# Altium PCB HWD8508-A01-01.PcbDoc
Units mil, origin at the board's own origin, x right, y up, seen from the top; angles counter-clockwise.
Board outline 2946.92 x 2010.03 mil, 2 copper layers (TopLayer, BottomLayer); 46 components, 92 nets, 462 pads, 19 vias.
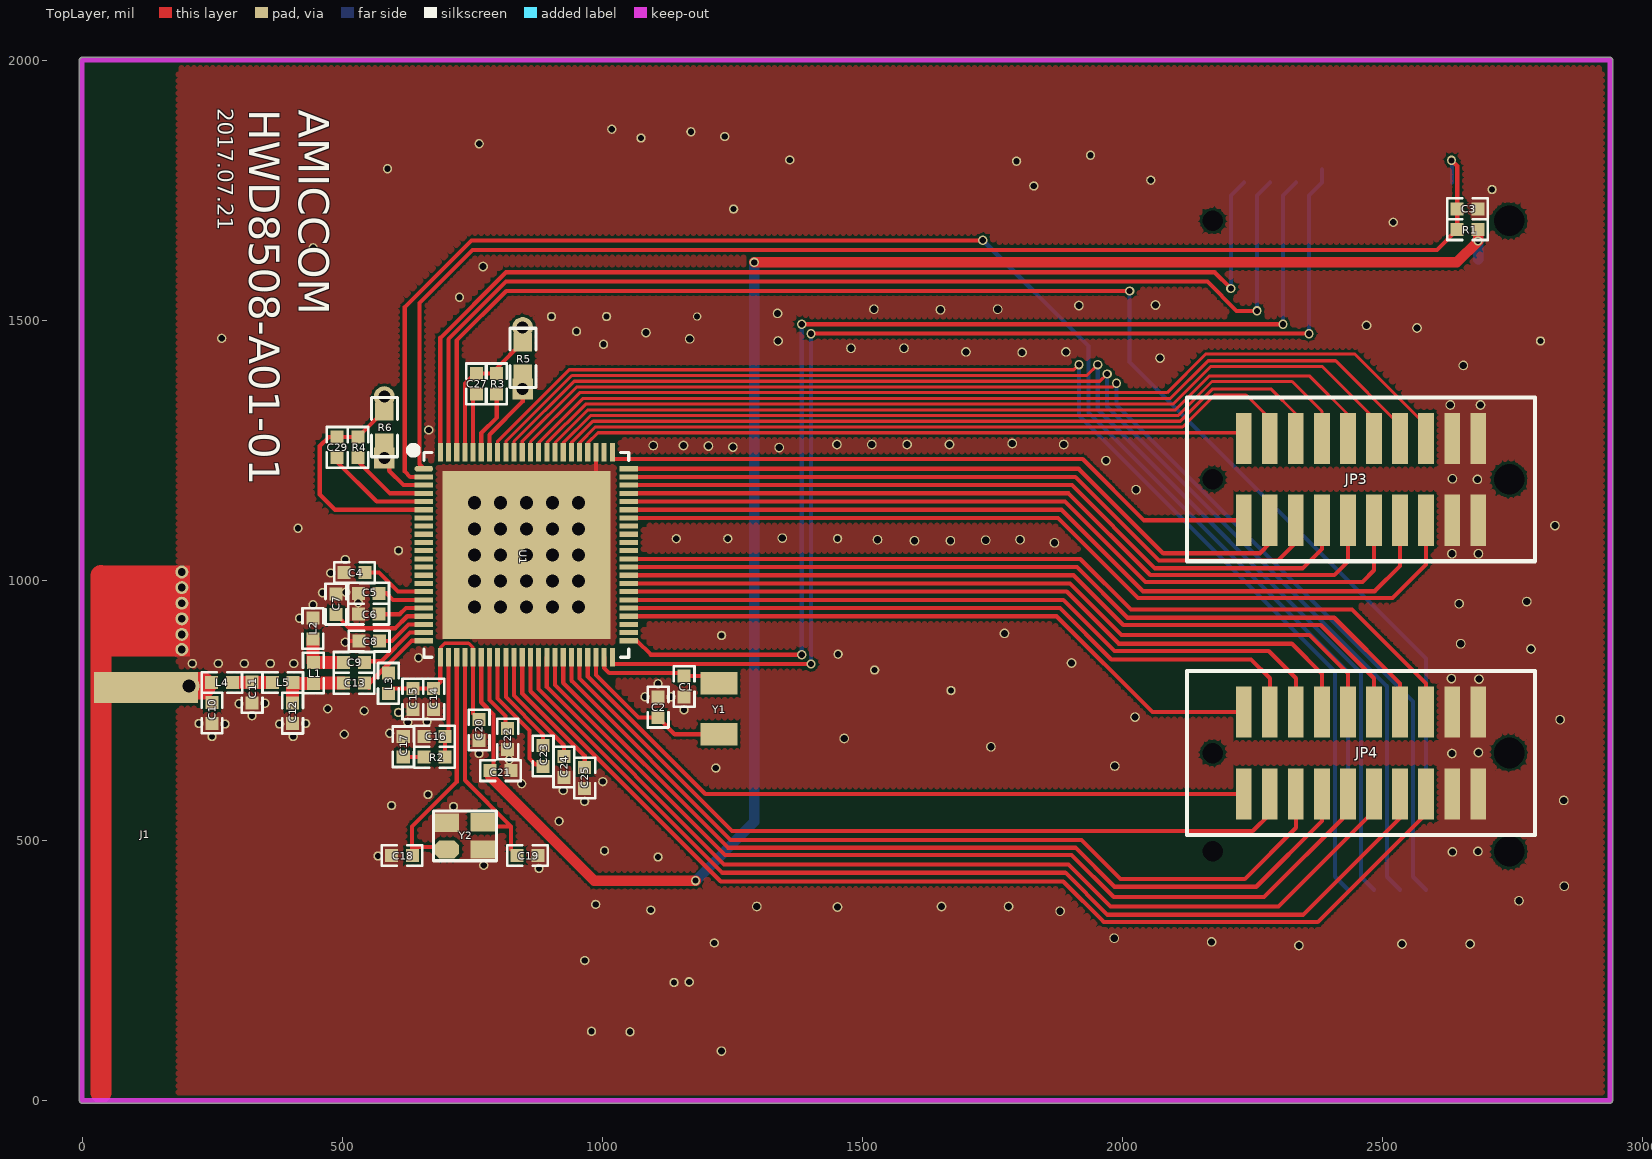
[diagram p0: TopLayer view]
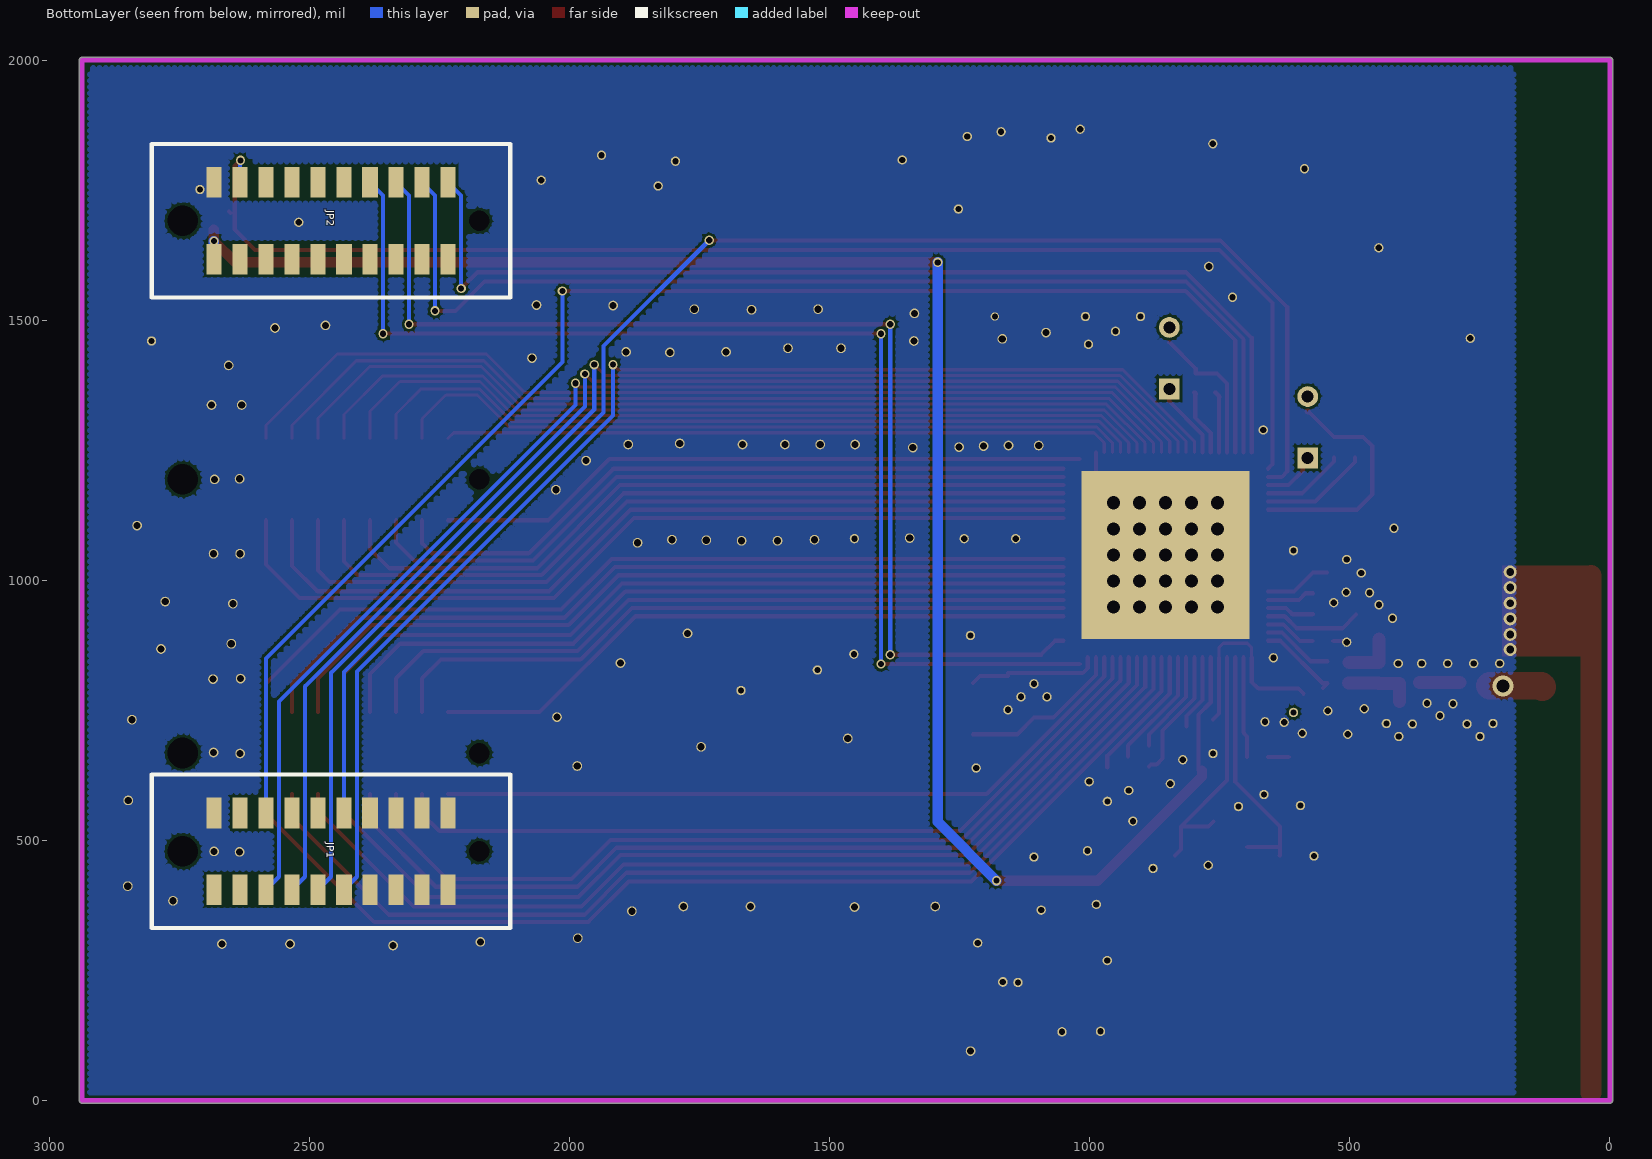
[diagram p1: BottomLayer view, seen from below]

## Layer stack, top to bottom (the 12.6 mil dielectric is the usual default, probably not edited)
TopSolder: solder mask 0.4, Solder Resist, Dk 3.5
TopLayer: signal copper 1.4
Dielectric1: dielectric 12.6, FR-4, Dk 4.8
BottomLayer: signal copper 1.4
BottomSolder: solder mask 0.4, Solder Resist, Dk 3.5

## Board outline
-5.01,0.34 ccw(c-0.01,0) -0.01,-5.01 2936.89,-5.01 ccw(c2936.89,0) 2941.91,0 2941.91,2000 ccw(c2936.89,2000) 2936.89,2005.01 -0.01,2005.01 ccw(c-0.01,2000) -5.01,1999.66

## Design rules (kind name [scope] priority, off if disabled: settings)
Clearance Clearance_4 [InNet('NetC19_1')] p1: gap=14
Clearance Clearance_3 [InNet('NetC18_2')] p2: gap=14
Clearance Clearance_2 [InNet('NetC4_2')] p3: gap=14
Clearance [All] p4 off: gap=8
Clearance Clearance_1 [All] p5: gap=5
ComponentClearance [All] p1 off: gap=10 collisioncheckmode=3 verticalgap=10 showdistances=FALSE
FabricationTestPointUsage TestPointUsage [All] p1: valid=0 allowmultiple=FALSE
FabricationTestpoint Testpoint [All] p1: side=3 testpointundercomponent=TRUE minsize=40 maxsize=100 preferedsize=60 minholesize=20 maxholesize=40 preferedholesize=32 testpointgrid=1 allowsidetop=TRUE allowsidebottom=TRUE usegrid=TRUE gridtolerance=0.01
HoleSize [All] p1: absolutevalues=TRUE maxlimit=200 minlimit=1 maxpercent=80.000 minpercent=20.000
PolygonConnect [All] p1: connectstyle=Direct reliefconductorwidth=10 reliefentries=4 polygonreliefangle="90 Angle" airgapwidth=10
RoutingVias [All] p1: holewidth=28 width=50 viastyle="Through Hole" minholewidth=28 minwidth=50 maxholewidth=28 maxwidth=50
SilkToSolderMaskClearance SilkscreenOverComponentPads [IsPad] p1: minsilkscreentomaskgap=10 clearancetoexposedcopper=TRUE
SolderMaskExpansion [All] p1: expansion=4
Width [All] p1: maxlimit=100 minlimit=6 preferedwidth=10
25 further rules are at their usual default settings.

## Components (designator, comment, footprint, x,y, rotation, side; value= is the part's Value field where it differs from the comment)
C1 "27p" 0402#1 1157.25,816.02 r270 top
C2 "27p" 0402#1 1107.25,736.02 r90 top
C3 "1U" 0402#1 2643.29,1714.02 r0 top
C4 "1uF" 0402#1 543.84,1014.71 r180 top
C5 "1uF" 0402#1 571.04,975.02 r180 top
C6 "330pF" 0402#1 571.04,935.02 r180 top (schematic designator C7)
C7 "120pF" 0402#1 488.04,934.02 r90 top
C8 "1uF" 0402#1 572.04,883.02 r180 top
C9 "2.7pF" 0402#1 542.84,842.23 r180 top
C10 "NC" 0402#1 249.84,724.71 r90 top
C11 "1pF" 0402#1 326.84,764.6 r90 top
C12 "1.2pF" 0402#1 404.84,764.6 r270 top
C13 "3.3pF" 0402#1 542.84,802.1 r180 top
C14 "100pF" 0402#1 676.04,792.02 r270 top
C15 "0.1uF" 0402#1 635.99,792 r270 top
C16 "3.3nF" 0402#1 697.45,700.02 r180 top
C17 "NC" 0402#1 617.45,660.02 r90 top
C18 "NC" 0402#1 635.04,471.02 r180 top
C19 "NC" 0402#1 836.04,471.02 r0 top
C20 "1uF" 0402#1 763.18,732.17 r270 top
C21 "1uF" 0402#1 784.18,634.17 r0 top
C22 "2.2uF" 0402#1 818.18,715.17 r270 top
C23 "47nF" 0402#1 886.18,642.17 r90 top (schematic designator C35)
C24 "1uF" 0402#2 926.18,641.17 r270 top (schematic designator C32)
C25 "1uF" 0402#2 966.18,620.17 r270 top (schematic designator C31)
C27 "NC" 0402#1 758.29,1397.58 r270 top (schematic designator C203)
C29 "820pF" 0402#1 490.43,1275.53 r270 top (schematic designator C103)
J1 "ANTENNA" ANT 122.84,793.94 r0 top
JP1 "HEADER 10X2B" YAB-V45P-2X 2173.45,479 r0 bottom locked
JP2 "HEADER 10X2B" YAB-V45P-2X 2173.45,1691 r0 bottom locked
JP3 "HEADER 10X2B" PAB-V16P-2X 2173.45,1194 r0 top locked
JP4 "HEADER 10X2B" PAB-V16P-2X 2173.45,668 r0 top locked
L1 "2.2nH" 0402#1 444.84,801.6 r90 top
L2 "1.2nH" 0402#1 443.84,887.6 r90 top
L3 "2.7nH" 0402#1 588.99,782 r90 top
L4 "1.8nH" 0402#1 248.84,803.6 r0 top
L5 "2.2nH" 0402#1 365.84,803.6 r0 top
R1 "100K" 0402#1 2683.29,1674.02 r180 top
R2 "NC" 0402#1 697.45,660.02 r180 top
R3 "NC" 0402#1 796.29,1357.58 r90 top (schematic designator R202)
R4 "10k" 0402#1 530.43,1235.53 r90 top (schematic designator R102)
R5 "NC" TR 847,1427 r0 top
R6 "NXRT15XH103FA1B" TR 581,1294 r0 top
U1 "A8508" "QFN 10*10 88L" 854.04,1049.02 r0 top
Y1 "32.768KHz" XTAL\32.768K\SMD 1224.11,704.06 r90 top (schematic designator Y2)
Y2 "16MHz, 9pF" XTAL_3.2*2.5 735.66,508.52 r270 top (schematic designator Y3)

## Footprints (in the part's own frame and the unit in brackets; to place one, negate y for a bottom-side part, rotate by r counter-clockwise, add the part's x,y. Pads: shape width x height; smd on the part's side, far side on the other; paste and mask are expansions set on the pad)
0402#1 [mil]
  rect 25x25 smd: 1(0,0) 2(40,0)
  silkscreen extent -19,-20 59,20
0402#2 [mil]
  rect 25x25 smd: 1(-20,0) 2(20,0)
  silkscreen extent -39,-20 39,20
ANT [mil]
  rect 200x60 smd: 1(0,0)
  TopLayer region: -43.41,234.83 -43.41,59.83 85.02,59.83 85.02,234.83
  TopLayer region: -78.98,60 -31.98,60 -31.98,210 -78.98,210
  TopLayer lines w40: -86.57,-779 -86.57,-708.42 -86.57,214.17 ; -86.57,215 65,214.83
PAB-V16P-2X [mm]
  rect 0.76x2.5 smd: 1(1.52,-2) 2(2.79,-2) 3(4.06,-2) 4(5.33,-2) 5(6.6,-2) 6(7.87,-2) 7(9.14,-2) 8(10.41,-2) 9(11.68,-2) 10(12.95,-2) 11(1.52,2) 12(2.79,2) 13(4.06,2) 14(5.33,2) 15(6.6,2) 16(7.87,2) 17(9.14,2) 18(10.41,2) 19(11.68,2) 20(12.95,2)
  oval 0x1 hole 1: ""(0,0)
  oval 0x1.5 hole 1.5: ""(14.47,0)
  silkscreen extent -1.26,-4 15.74,4
"QFN 10*10 88L" [mm]
  oct 0.9x0.25 smd: 1(-5,4.2)
  rect 0.9x0.25 smd: 2(-5,3.8) 3(-5,3.4) 4(-5,3) 5(-5,2.6) 6(-5,2.2) 7(-5,1.8) 8(-5,1.4) 9(-5,1) 10(-5,0.6) 11(-5,0.2) 12(-5,-0.2) 13(-5,-0.6) 14(-5,-1) 15(-5,-1.4) 16(-5,-1.8) 17(-5,-2.2) 18(-5,-2.6) 19(-5,-3) 20(-5,-3.4) 21(-5,-3.8) 22(-5,-4.2) 45(5,-4.2) 46(5,-3.8) 47(5,-3.4) 48(5,-3) 49(5,-2.6) 50(5,-2.2) 51(5,-1.8) 52(5,-1.4) 53(5,-1) 54(5,-0.6) 55(5,-0.2) 56(5,0.2) 57(5,0.6) 58(5,1) 59(5,1.4) 60(5,1.8) 61(5,2.2) 62(5,2.6) 63(5,3) 64(5,3.4) 65(5,3.8) 66(5,4.2)
  rect 0.25x0.9 smd: 23(-4.2,-5) 24(-3.8,-5) 25(-3.4,-5) 26(-3,-5) 27(-2.6,-5) 28(-2.2,-5) 29(-1.8,-5) 30(-1.4,-5) 31(-1,-5) 32(-0.6,-5) 33(-0.2,-5) 34(0.2,-5) 35(0.6,-5) 36(1,-5) 37(1.4,-5) 38(1.8,-5) 39(2.2,-5) 40(2.6,-5) 41(3,-5) 42(3.4,-5) 43(3.8,-5) 44(4.2,-5) 67(4.2,5) 68(3.8,5) 69(3.4,5) 70(3,5) 71(2.6,5) 72(2.2,5) 73(1.8,5) 74(1.4,5) 75(1,5) 76(0.6,5) 77(0.2,5) 78(-0.2,5) 79(-0.6,5) 80(-1,5) 81(-1.4,5) 82(-1.8,5) 83(-2.2,5) 84(-2.6,5) 85(-3,5) 86(-3.4,5) 87(-3.8,5) 88(-4.2,5)
  round 0.635 hole 0.635: ""(-2.54,-2.54) ""(-2.54,-1.27) ""(-2.54,0) ""(-2.54,1.27) ""(-2.54,2.54) ""(-1.27,-2.54) ""(-1.27,-1.27) ""(-1.27,0) ""(-1.27,1.27) ""(0,-2.54) ""(0,-1.27) ""(0,1.27) ""(0,2.54) ""(1.27,-2.54) ""(1.27,-1.27) ""(1.27,0) ""(1.27,1.27) ""(1.27,2.54) ""(2.54,-2.54) ""(2.54,-1.27) ""(2.54,0) ""(2.54,1.27) ""(2.54,2.54)
  round 0.762 hole 0.635: ""(-1.27,2.54)
  rect 8.2x8.2 hole 0.635: ""(0,0)
  silkscreen extent -5.62,-5 5,5.21
TR [mil]
  rect 40x40 hole 23: 1(0,-59.06)
  rect 35x35 smd: 1(0,-29.5) 2(0,30.5)
  round 40 hole 23: 2(0,59.06)
  silkscreen extent -24,-56 26,58
XTAL\32.768K\SMD [mm]
  rect 1.1x1.8 smd: 1(0,0) 2(2.5,0)
XTAL_3.2*2.5 [mm]
  oct 0.9x1.2 smd: 1(0.66,-0.87)
  rect 0.9x1.2 smd: 2(0.66,0.87) 3(-0.66,0.87) 4(-0.65,-0.87)
  silkscreen extent -1.22,-1.53 1.21,1.55
YAB-V45P-2X [mm]
  rect 0.74x1.5 smd: 1(1.52,1.875) 2(2.79,1.875) 3(4.06,1.875) 4(5.33,1.875) 6(7.87,1.875) 7(9.14,1.875) 8(10.41,1.875) 9(11.68,1.875) 10(12.95,1.875) 11(1.52,-1.875) 12(2.79,-1.875) 13(4.06,-1.875) 15(6.6,-1.875) 16(7.87,-1.875) 17(9.14,-1.875) 18(10.41,-1.875) 19(11.68,-1.875) 20(12.95,-1.875)
  rect 0.76x1.5 smd: 5(6.6,1.875) 14(5.33,-1.875)
  oval 0x1 hole 1: ""(0,0)
  oval 0x1.5 hole 1.5: ""(14.47,0)
  silkscreen extent -1.52,-3.75 15.98,3.75

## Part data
C1 C2 C23: library part C/0603, "Chip C"
C3: library part C/0402, "Chip C"
C4 C5 C6 C7 C8 C9 C10 C11 C12 C13 C14 C15 C16 C17 C18 C19 C20 C21 C22 C24 C25 C27 C29: library part CAP
JP1 JP2 JP3 JP4: "Pitch 2.54mm"
L1 L2 L3 L4 L5: library part L/0402, "Chip L"
R1: library part R/0603, "Chip  R"
R2 R3 R4 R5 R6: library part RES1
U1: library part "ams100_3a wo DCDC"
Y1: library part CRYSTAL, "Crystal"
Y2: library part CRYSTAL/5*3.2

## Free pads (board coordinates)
  round 18 hole 12: A(212.04,840.02) A(224.8,724.71) A(249.8,699.71) A(262.04,840.02) A(268.45,1465.02) A(274.8,723.71) A(301.8,762.71) A(312.04,840.02) A(326.8,739.71) A(351.8,763.71) A(362.04,840.02) A(379.8,723.71) A(405.8,699.71) A(407.04,840.02) A(415.29,1100.02) A(418.04,927.02) A(429.8,724.71) A(444.04,953.02) A(444.29,1639.02) A(462.04,976.02) A(472.29,753.02) A(478.04,1014.02) A(503.99,704) A(506.04,881.02) A(507.04,977.02) A(531.04,957.02) A(542.29,749.02) A(569.04,470.02) A(587.29,1791.02) A(591.29,706.02) A(595.04,567.02) A(608.29,1057.02) A(626.29,727.02) A(646.99,851) A(663.29,728.02) A(665.18,588.17) A(666.45,1289.02) A(714.04,565.02) A(725.45,1544.02) A(763.04,667.02) A(763.29,1839.02) A(772.18,452.17) A(821.04,655.02) A(845.04,609.02) A(878.18,446.17) A(902.29,1507.02) A(917.04,537.02) A(925.04,596.02) A(950.43,1478.47) A(966.04,575.02) A(966.29,269.02) A(979.29,133.02) A(987.29,377.02) A(1001.04,613.02) A(1002.43,1453.47) A(1004.29,480.02) A(1008.29,1507.02) A(1018.29,1867.02) A(1053.29,132.02) A(1074.29,1850.02) A(1082.25,776.02) A(1093.29,366.02) A(1107.25,801.02) A(1107.29,468.02) A(1132.25,776.02) A(1137.99,227) A(1142.29,1080.02) A(1157.25,751.02) A(1170.29,1862.02) A(1215.29,303.02) A(1218.29,639.02) A(1229.29,894.02) A(1235.29,1853.02) A(1241.29,1080.02) A(1252.43,1713.47) A(1360.29,1808.02) A(1452.29,1080.02) A(1453.29,858.02) A(1523.43,827.47) A(1670.29,788.02) A(1796.29,1805.58) A(1829.43,1758.02) A(1938.29,1817.02) A(2054.29,1769.02) A(2520.29,1688.02) A(2710.29,1751.02) A(2803.29,1460.02) ""(608.29,746.02)
  round 18 hole 12 mask+4: A(506.04,1040.02)
  round 18.7 hole 13.78: A(771,1603) A(1084,1476) A(1098,1259) A(1156,1259) A(1168,1464) A(1204,1258) A(1229,95) A(1251,1256) A(1297,373) A(1337,1513) A(1338,1460) A(1340,1255) A(1346,1081) A(1451,1261) A(1452,372) A(1465,696) A(1478,1446) A(1518,1261) A(1522,1521) A(1529,1078) A(1580,1446) A(1586,1261) A(1600,1076) A(1650,1520) A(1652,373) A(1667.26,1261) A(1669,1076) A(1699,1439) A(1737,1077) A(1747,680) A(1760,1521) A(1773,898) A(1781,373) A(1788,1263) A(1803,1078) A(1807,1438) A(1869,1072.05) A(1880,364) A(1887,1261) A(1891,1439) A(1902,841) A(1916,1528.05) A(1968,1230) A(1984,312) A(1985,643) A(2024,737) A(2026,1174) A(2063.26,1529) A(2072,1427) A(2171.26,305) A(2339,298) A(2469,1490) A(2537,301) A(2566,1485) A(2630,1337) A(2632,811) A(2633,667) A(2633,1051) A(2634,478) A(2634,1195) A(2647,955) A(2650,878) A(2655,1413) A(2668,301) A(2682,1194) A(2683,479) A(2684,669) A(2684,1051) A(2685,810) A(2688,1337) A(2762,384) A(2777,959) A(2785,868) A(2831,1105) A(2841,732) A(2848,577) A(2849,412)
  round 18.7 hole 12.01: A(1167,228)
  round 16 hole 12: A(1182.29,1507.02)
  round 25 hole 15: ""(191.84,866.94) ""(191.84,895.94) ""(191.84,925.94) ""(191.84,955.94) ""(191.84,985.94) ""(191.84,1015.94)

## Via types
v1: diameter 18, hole 12, TopLayer to BottomLayer, tented both sides, 18 vias
v2: diameter 40, hole 25, TopLayer to BottomLayer, 1 vias

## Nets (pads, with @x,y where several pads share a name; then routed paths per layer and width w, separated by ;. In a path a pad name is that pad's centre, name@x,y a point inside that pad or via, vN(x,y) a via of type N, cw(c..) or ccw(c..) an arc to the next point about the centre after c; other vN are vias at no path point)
BG: C6.1 U1.18 | length 91.2
  TopLayer w8: C6.1 571.34,934.71 610.58,934.71 622.52,946.65 U1.18
CP_LCD: C25.1 U1.33 | length 261.7
  TopLayer w8: U1.33 846.16,782.7 966.18,662.68 C25.1
CPPA: C23.1 U1.30 | length 252.6
  TopLayer w8: U1.30 798.92,772.75 860.18,711.49 860.18,657.17 871.18,646.17 882.18,646.17 C23.1
CPPB: C23.2 U1.31 | length 199.6
  TopLayer w8: U1.31 814.67,775.39 886.18,703.87 C23.2
GND: C1.2 C2.2 C3.2 C4.2 C5.2 C6.2 C7.2 C8.2 C10.1 C11.1 C12.2 C14.2 C15.2 C16.2 C17.2 C18.2 C19.2 C20.2 C21.2 C22.2 C24.2 C25.2 JP1.1 JP1.2 JP1.3 JP1.4 JP1.11 JP1.12 JP1.13 JP1.14 JP1.20 JP2.20 JP3.9 JP3.10 JP3.19 JP3.20 JP4.9 JP4.10 JP4.19 JP4.20 L2.2 pad.@191.84,866.94 pad.@191.84,895.94 pad.@191.84,925.94 pad.@191.84,955.94 pad.@191.84,985.94 pad.@191.84,1015.94 pad.A U1. U1.69 Y2.2 Y2.4 | length 137.7
  TopLayer w8: pad.A@506.04,881.02 508.04,883.02 C8.2 ; U1.@954.04,1149.02 987.89,1182.87 U1.69
LCDCAP_R33: C22.1 U1.29 | length 145.8
  TopLayer w8: U1.29 783.17,770.11 814.18,739.1 C22.1@814.18,719.17
LPF: C16.1 R2.1 U1.24 | length 195
  TopLayer w8: R2.1 C16.1 704.43,707 U1.24
NetC9_2: C9.2 L1.2 L2.1 | length 103
  TopLayer w25: L1.2@443.84,842.23 C9.2@501.84,842.23 ; L1.2@443.84,842.6 L2.1
NetC10_2: C10.2 J1.1 L4.1 | length 101.8
  TopLayer w53: J1.1@129.84,794.94 131.84,796.94 v2(205.84,796.94) 230.84,796.94
NetC11_2: C11.2 L4.2 L5.1 | length 78
  TopLayer w25: L4.2@287.84,803.6 L4.2 L5.1
NetC12_1: C12.1 C13.2 L1.1 L5.2 | length 133
  TopLayer w25: C12.1@404.84,766.6 404.84,801.6 L1.1 ; L1.1@444.84,802.1 C13.2
NetC17_1: C17.1 R2.2 | length 40
  TopLayer w8: C17.1 R2.2
P0.0: C29.1 R4.2 R6.2 U1.6 | length 457.4
  TopLayer w8: R6.2@581,1324.5 579.4,1324.5 R4.2 C29.1 474.53,1275.53 457,1258 457,1165 486.37,1135.63 U1.6
  TopLayer w12: R6.2@581,1324.5 R6.2@581.5,1324.5
P0.1: C29.2 U1.5 | length 206.3
  TopLayer w8: C29.2 490.43,1227.47 566.52,1151.38 U1.5
P0.2: R4.1 U1.4 | length 159.2
  TopLayer w8: R4.1 530.43,1228.47 591.78,1167.13 U1.4
P0.3: R6.1 U1.3 | length 106.5
  TopLayer w8: R6.1@581,1234.94 590.43,1225.52 590.43,1210.56 618.11,1182.87 U1.3
P0.4/DEBUG_EN: JP1.15 U1.2 | length 2912.5
  TopLayer w8: U1.2 630.75,1198.62 620.45,1208.93 620.45,1525.02 748.45,1653.02 v1@1731.29,1653.02
  BottomLayer w8: v1(1731.29,1653.58) 1934.29,1450.58 1934.29,1322.58 2433.29,823.58 JP1.15
P0.5: JP2.11 U1.88 | length 2019.2
  TopLayer w8: U1.88 688.68,1466.02 814.68,1592.02 2177.1,1592.02 v1(2208.29,1560.82)
  BottomLayer w8: v1(2208.29,1560.82) 2208.29,1739.82 JP2.11
P0.6: JP2.12 U1.87 | length 2097.8
  TopLayer w8: U1.87 704.43,1463.38 815.06,1574.02 2163.1,1574.02 2219.29,1517.82 v1(2258.29,1517.82)
  BottomLayer w8: v1(2258.29,1517.82) 2258.29,1739.82 JP2.12
P0.7/GIO1: JP1.18 U1.86 | length 2786.9
  TopLayer w8: U1.86 720.18,1460.75 815.45,1556.02 v1(2013.51,1556.02)
  BottomLayer w8: v1(2013.51,1556.02) 2013.51,1419.49 2583.29,849.7 JP1.18
P1.0: C27.1 R3.2 R5.2 U1.85 | length 282.6
  TopLayer w8: U1.85 735.93,1377.98 755.53,1397.58 C27.1 R3.2 796.29,1406.79 R5.2@847,1457.5 ; R5.2@847,1485 R5.2@847,1486.06
P1.1: C27.2 U1.84 | length 129.5
  TopLayer w8: C27.2@750.67,1352.24 C27.2@751.67,1353.24 ; U1.84 C27.2@751.67,1353.24 ; C27.2@757.29,1360.58 751.67,1354.96 C27.2@751.67,1353.24 ; C27.2@759.45,1361.02 C27.2@751.67,1353.24
P1.2/GIO2: R3.1 U1.83 | length 131.5
  TopLayer w8: U1.83 767.42,1282.99 797.29,1312.87 R3.1@797.29,1358.87 ; R3.1@796.29,1357.87 R3.1@797.29,1358.87 ; R3.1@797.29,1360.58 R3.1@797.29,1358.87 ; R3.1@799.45,1361.02 R3.1@797.29,1358.87
P1.3/CKO: R5.1 U1.82 | length 148.5
  TopLayer w8: U1.82 783.17,1279.74 847,1343.57 R5.1@847,1367.94
P1.4/TTDIO: JP1.5 U1.81 | length 2423.3
  TopLayer w6: U1.81 798.92,1267.21 936.29,1404.58 1906.29,1404.58 v1(1916.29,1414.58)
  BottomLayer w8: v1(1916.29,1414.58) 1916.29,1316.58 2408.29,824.58 2408.29,430.18 JP1.5
P1.5/TTCLK: JP1.6 U1.80 | length 2449.1
  TopLayer w6: U1.80 814.67,1266.76 941.49,1393.58 1931.29,1393.58 v1(1952.29,1414.58)
  BottomLayer w8: v1(1952.29,1414.58) 1952.29,1328.18 2458.29,822.18 2458.29,430.18 JP1.6
P1.6: JP1.7 U1.79 | length 2439.3
  TopLayer w6: U1.79 830.41,1266.95 946.04,1382.58 1956.29,1382.58 v1(1970.29,1396.58)
  BottomLayer w8: v1(1970.29,1396.58) 1970.29,1334.18 2508.29,796.18 2508.29,430.18 JP1.7
P1.7: JP1.8 U1.78 | length 2429.4
  TopLayer w6: U1.78 846.16,1267.15 950.6,1371.58 1981.29,1371.58 v1(1988.29,1378.58)
  BottomLayer w8: v1(1988.29,1378.58) 1988.29,1337.18 2558.29,767.18 2558.29,430.18 JP1.8
P2.0/C0: JP3.18 U1.77 | length 1893.6
  TopLayer w6: U1.77 861.91,1265.95 956.54,1360.58 2085.58,1360.58 2160,1435 2446.52,1435 2583.3,1298.23 JP3.18
P2.1/C1: JP3.17 U1.76 | length 1816
  TopLayer w6: U1.76 877.66,1264.07 963.17,1349.58 2092.21,1349.58 2164.63,1422 2409.52,1422 2533.3,1298.23 JP3.17
P2.2/C2: JP3.16 U1.75 | length 1749
  TopLayer w6: U1.75 893.41,1264.07 967.92,1338.58 2096.96,1338.58 2169.38,1411 2384,1411 2483.3,1311.7 JP3.16
P2.3/C3: JP3.15 U1.74 | length 1672.5
  TopLayer w6: U1.74 909.15,1264.07 972.67,1327.58 2101.71,1327.58 2167.13,1393 2359,1393 2433.3,1318.7 JP3.15
P2.4/S0: JP3.14 U1.73 | length 1601.2
  TopLayer w6: U1.73 924.9,1264.07 977.41,1316.58 2106.46,1316.58 2171.88,1382 2326.05,1382 2383.3,1324.76 JP3.14
P2.5/S1: JP3.13 U1.72 | length 1521
  TopLayer w6: U1.72 940.65,1264.25 981.98,1305.58 2111.03,1305.58 2173.44,1368 2285,1368 2333.3,1319.7 JP3.13
P2.6/S2: JP3.12 U1.71 | length 1439.8
  TopLayer w6: U1.71 956.4,1264.44 986.54,1294.58 2115.58,1294.58 2177,1356 2237.48,1356 2283.3,1310.18 JP3.12
P2.7/S3: JP3.11 U1.70 | length 1291.9
  TopLayer w6: U1.70 972.15,1264.07 991.66,1283.58 2222.45,1283.58 JP3.11
P3.0: U1.47
P3.1: U1.46
P3.2: JP2.13 U1.45 | length 2186.6
  TopLayer w8: U1.45 1066.6,883.66 1093.25,857.02 v1(1383.29,857.02) ; v1(1383.29,1492.02) v1(2308.29,1492.02)
  BottomLayer w8: v1(1383.29,857.02) v1(1383.29,1492.02) ; v1(2308.29,1492.02) 2308.29,1739.82 JP2.13
P3.3: JP2.14 U1.44 | length 2300.1
  TopLayer w8: U1.44@1019.25,839.02 v1(1401.29,839.02) ; v1(1401.29,1474.02) v1(2358.29,1474.02)
  BottomLayer w8: v1(1401.29,839.02) v1(1401.29,1474.02) ; v1(2358.29,1474.02) 2358.29,1739.82 JP2.14 JP2.14@2383.29,1789.76
P3.6: C1.1 U1.43 Y1.2 | length 250.6
  TopLayer w8: U1.43 1003.64,831.62 1013.25,822.02 C1.1@1157.25,822.02 ; C1.1 1210.58,816.02 Y1.2
P3.7: C2.1 U1.42 Y1.1 | length 317.7
  TopLayer w8: U1.42 987.89,817.74 1069.62,736.02 C2.1 1139.2,704.06 Y1.1
REGI: C21.1 JP2.10 R1.1 U1.28 | length 3416.8
  TopLayer w8: U1.28 767.42,765.65 791.18,741.89 C21.1@791.18,634.17
  TopLayer w20: C21.1 784.18,623.17 984.52,422.82 v1(1179.29,422.82) ; v1(1292.29,1611.02) 2642.29,1611.02 v1(2683.29,1652.02) R1.1
  BottomLayer w20: v1(1179.29,422.82) 1292.29,535.82 v1(1292.29,1611.02) ; JP2.10 v1(2683.29,1652.02)
REGO: C24.1 U1.32 | length 230.7
  TopLayer w8: U1.32 830.41,778.65 926.18,682.89 C24.1
RESETN: C3.1 JP2.19 R1.2 U1.1 | length 2559.5
  TopLayer w8: U1.1 648.45,1223.11 648.45,1533.02 750.45,1635.02 2604.29,1635.02 R1.2 C3.1 2643.29,1796.02 v1(2632.29,1807.02) ; C3.1@2651.27,1706.04 C3.1@2654.25,1709.02
  BottomLayer w8: JP2.19 v1@2633.29,1807.02
RFI: C9.1 U1.21 | length 137.2
  TopLayer w8: C9.1@542.84,844.34 575.36,844.34 630.43,899.41 U1.21
RFO: C13.1 L3.2 U1.22 | length 161
  TopLayer w8: C13.1@551.93,793.02 C13.1 552.12,802.1 633.68,883.66 U1.22
S0.0: JP3.1 U1.67 | length 1262.6
  TopLayer w8: U1.67@1019.45,1233.02 1923.44,1233.02 2041.19,1115.26 JP3.1
S0.1: JP3.2 U1.66 | length 1351.6
  TopLayer w8: U1.66 1915.71,1214.37 2078.08,1052 2264,1052 2283.3,1071.3 JP3.2
S0.2: JP3.3 U1.65 | length 1406.1
  TopLayer w8: U1.65 1909.19,1198.62 2069.81,1038 2299,1038 2333.3,1072.3 JP3.3
S0.3: JP3.4 U1.64 | length 1469
  TopLayer w8: U1.64 1902.67,1182.87 2062.54,1023 2346,1023 2383.3,1060.3 JP3.4
S0.4: JP3.5 U1.63 | length 1537.3
  TopLayer w8: U1.63 1896.15,1167.13 2053.27,1010 2407,1010 2433.3,1036.3 JP3.5
S0.5: JP3.6 U1.62 | length 1601.6
  TopLayer w8: U1.62 1889.62,1151.38 2044,997 2461,997 2483.3,1019.3 JP3.6
S0.6: JP3.7 U1.61 | length 1655
  TopLayer w8: U1.61 1882.37,1135.63 2039,979 2484.62,979 2533.3,1027.68 JP3.7
S0.7: JP3.8 U1.60 | length 1707.7
  TopLayer w8: U1.60 1875.85,1119.88 2029.73,966 2519,966 2583.3,1030.3 JP3.8
S1.0: JP4.18 U1.55 | length 1686.6
  TopLayer w8: U1.55 1918.76,1041.14 2015.95,943.95 2441.05,943.95 2583.3,801.7 JP4.18
S1.1: JP4.17 U1.54 | length 1630
  TopLayer w8: U1.54 1912.23,1025.39 2009.57,928.05 2406.95,928.05 2533.3,801.7 JP4.17
S1.2: JP4.16 U1.53 | length 1579.4
  TopLayer w8: U1.53 1905.71,1009.65 2001.36,914 2381,914 2483.3,811.7 JP4.16
S1.3: JP4.15 U1.52 | length 1528.1
  TopLayer w8: U1.52 1899.19,993.9 1998.08,895 2359,895 2433.3,820.7 JP4.15
S1.4: JP4.14 U1.51 | length 1471.2
  TopLayer w8: U1.51 1892.66,978.15 1992.81,878 2325.35,878 2383.3,820.05 JP4.14
S1.5: JP4.13 U1.50 | length 1409.8
  TopLayer w8: U1.50 1886.14,962.4 1984.54,864 2281,864 2333.3,811.7 JP4.13
S1.6: JP4.12 U1.49 | length 1353.3
  TopLayer w8: U1.49 1879.62,946.65 1978.27,848 2247,848 2283.3,811.7 JP4.12
S1.7: JP4.11 U1.48 | length 1258.7
  TopLayer w8: U1.48 1873.09,930.91 2057.26,746.74 JP4.11
S2.0: JP4.1 U1.41 | length 1391.8
  TopLayer w8: U1.41 972.15,815.11 1197.99,589.26 JP4.1
S2.1: JP4.2 U1.40 | length 1541.3
  TopLayer w8: U1.40 956.4,811.06 1249.45,518 2250.26,518 2283.3,551.04 JP4.2
S2.2: JP4.3 U1.39 | length 1701.3
  TopLayer w8: U1.39 940.65,807 1246.65,501 1921,501 1996,426 2235,426 2333.3,524.3 JP4.3
S2.3: JP4.4 U1.38 | length 1774.2
  TopLayer w8: U1.38 924.9,802.95 1241.86,486 1909.26,486 1984.26,411 2257,411 2383.3,537.3 JP4.4
S2.4: JP4.5 U1.37 | length 1850.1
  TopLayer w8: U1.37 909.15,798.9 1236.06,472 1902,472 1983,391 2272,391 2433.3,552.3 JP4.5
S2.5: JP4.6 U1.36 | length 1930.8
  TopLayer w8: U1.36 893.41,794.85 1234.26,454 1896,454 1977,373 2300,373 2483.3,556.3 JP4.6
S2.6: JP4.7 U1.35 | length 2019.8
  TopLayer w8: U1.35 877.66,790.8 1230.46,438 1890,438 1971,357 2347,357 2533.3,543.3 JP4.7
S2.7: JP4.8 U1.34 | length 2095
  TopLayer w8: U1.34 861.91,786.75 1227.66,421 1886,421 1964,343 2375.33,343 2583.3,550.96 JP4.8
S3.0: U1.59
S3.1: U1.58
S3.2: U1.57
S3.3: U1.56
S3.4: U1.68
S3.5: U1.7
S3.6: U1.8
S3.7: U1.9
S4.0: U1.10
S4.1: U1.11
S4.2: U1.12
S4.3: U1.13
S4.4: U1.14
S4.5: U1.15
VDD_A: C8.1 U1.20 | length 98.5
  TopLayer w8: C8.1 595.65,883.02 627.79,915.16 U1.20
VDD_D: C5.1 U1.17 | length 91.4
  TopLayer w8: C5.1 585.04,975.02 597.65,962.4 U1.17
VDD_P: C14.1 C15.1 C20.1 L3.1 U1.23 U1.27 | length 387.9
  TopLayer w6: U1.23 688.68,870.37 697.33,879.02 743.03,879.02 751.67,870.37 U1.27
  TopLayer w8: L3.1 598.99,792 C15.1 C14.1@676.02,792 ; C14.1 688.68,804.66 U1.23 ; U1.27 751.67,743.67 C20.1
VDD_R: C7.1 U1.19 | length 189.7
  TopLayer w8: C7.1 514.34,907.71 601.96,907.71 625.16,930.91 U1.19
VDD_S: C4.1 U1.16 | length 128.5
  TopLayer w8: C4.1 571.02,1014.71 607.59,978.15 U1.16
XI: C18.1 U1.25 Y2.1 | length 478.9
  TopLayer w8: C18.1 634.45,471.61 634.45,526.66 720.18,612.39 U1.25 ; 635.18,487.3 Y2.1@697.19,487.3
XO: C19.1 U1.26 Y2.3 | length 489.1
  TopLayer w8: U1.26 735.93,615.6 824.66,526.87 ; Y2.3@762.15,536.52 771.8,526.87 824.66,526.87 ; C19.1 824.66,482.39 824.66,526.87
pads on no net: JP1. JP1.9 JP1.10 JP1.16 JP1.17 JP1.19 JP2. JP2.1 JP2.2 JP2.3 JP2.4 JP2.5 JP2.6 JP2.7 JP2.8 JP2.9 JP2.15 JP2.16 JP2.17 JP2.18 JP3. JP4.

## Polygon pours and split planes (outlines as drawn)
GND on BottomLayer "TopLayer-No Net" (hatched 90Degree grid 12 track 12, remove dead copper, pour order 6): 2930,0.42 2930,2000.42 186,2000.42 186,0.42 2930,0.42
GND on TopLayer "TopLayer-No Net" (hatched 90Degree grid 12 track 12, remove dead copper, pour order 8): 2930,0.42 2930,2000.42 186,2000.42 186,0.42 2930,0.42

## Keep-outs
KeepOutLayer:
  lines w10: 180.99,0 2936.89,0 2936.89,2000 180.99,2000 ; 2480.3,0 -0.01,0 0,2000 2480.3,2000

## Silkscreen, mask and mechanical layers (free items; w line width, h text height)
TopOverlay:
  text "2017.07.21" at 261,1907 h30 r270
  text "HWD8508-A01-01" at 321,1905 h59.06 r270
  text "AMICCOM" at 417,1904 h59.06 r270
TopSolder:
  rectangle: 180.25,572.88 279.25,672.88
  rectangle: 180.25,921 279.25,1021
BottomSolder:
  rectangle: 177.25,483 284.25,1107
Mechanical1:
  lines w10: 180.84,0 180.84,2000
